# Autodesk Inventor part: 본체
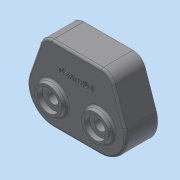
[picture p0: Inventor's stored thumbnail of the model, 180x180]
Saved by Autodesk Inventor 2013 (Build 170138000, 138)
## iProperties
Created: 2014-12
Part Number: 본체
Material: 일반
Document SubType Name: Modeling
Designer: dgall
Density: 1 g/cm^3
Author: dgall
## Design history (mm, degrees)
sketch "스케치1"
  geometry: L1 (0, 0)-(0, 36.035); L2 (0, 0)-(0, -46); L3 (0, 0)-(-32.527, -32.527); L4 (0, 0)-(32.527, -32.527); L5 (47, 36)-(-47, 36); L6 (-47, 36)-(-66.565, -20.803); L7 (47, 36)-(67.678, -24.037); L8 (-32.527, -68.527)-(32.527, -68.527); A1 r 46 centre (0, 0) between (-28.636, 36) and (28.636, 36); A2 r 36 centre (-32.527, -32.527) between (-66.565, -20.803) and (-32.527, -68.527); A3 r 36 centre (32.527, -32.527) between (32.527, -68.527) and (66.565, -20.803); 2 further points
  constraints: 16 end point, 9 point on circle, 3 centre point, 3 coincident, 3 point on line, 3 tangent, 1 collinear, 1 midpoint, 1 parallel, 1 perpendicular, 1 vertical, 1 vertical alignment
  dimensions: "d0" = 46 radius of A1; "d4" = 45 deg angle of L2 L3; "d6" = 45 deg angle of L4 L2; "d8" = 36 radius of A2; "d9" = 94 distance of L5.start L5.end; "d10" = 36 distance from line of L5 point (0, 0); "d11" = 36 radius of A3
extrude "돌출1" new body sketch "스케치1" distance "d12" = 44; taper "d13" = 0 deg
sketch "스케치2"
  geometry: L1 (-47, 36)-(47, 36) reference; L2 (-66.565, -20.803)-(-47, 36) reference; L3 (32.527, -68.527)-(-32.527, -68.527) reference; L4 (47, 36)-(66.565, -20.803) reference; L5 (43.434, 31)-(-43.434, 31); L6 (-43.434, 31)-(-61.837, -22.432); L7 (-32.527, -63.527)-(32.527, -63.527); L8 (61.837, -22.432)-(43.434, 31); A1 r 36 centre (-32.527, -32.527) between (-66.565, -20.803) and (-32.527, -68.527) reference; A2 r 36 centre (32.527, -32.527) between (32.527, -68.527) and (66.565, -20.803) reference; A3 r 31 centre (-32.527, -32.527) between (-61.837, -22.432) and (-32.527, -63.527); A4 r 31 centre (32.527, -32.527) between (32.527, -63.527) and (61.837, -22.432); 1 further point
  constraints: 8 end point, 4 point on circle, 2 centre point, 5 other
  dimensions: "d14" = 5 distance between parallel lines of L1 L5
extrude "돌출2" cut sketch "스케치2" distance "d15" = 34; taper "d16" = 0 deg
sketch "스케치3"
  geometry: A1 r 31 centre (-32.527, -32.527) between (-61.837, -22.432) and (-32.527, -63.527) reference; A2 r 31 centre (32.527, -32.527) between (32.527, -63.527) and (61.837, -22.432) reference; A3 r 24 centre (-32.527, -32.527) between (-26.959, -9.182) and (-9.182, -26.959); A4 r 24 centre (32.527, -32.527) between (9.182, -26.959) and (26.959, -9.182); A5 r 3 centre (-26.263, -6.263) between (-26.959, -9.182) and (-23.345, -5.568); A6 r 3 centre (26.263, -6.263) between (23.345, -5.568) and (26.959, -9.182); A7 r 3 centre (-6.263, -26.263) between (-5.568, -23.345) and (-9.182, -26.959); A8 r 3 centre (6.263, -26.263) between (9.182, -26.959) and (5.568, -23.345); A9 r 24 centre (0, 0) between (-5.568, -23.345) and (5.568, -23.345); A10 r 24 centre (0, 0) between (23.345, -5.568) and (-23.345, -5.568); 1 further point
  constraints: 16 point on circle, 8 centre point, 8 tangent, 3 coincident
  dimensions: "d19" = 48 diameter of A4; "d20" = 48 diameter of A3; "d21" = 3 radius of A5; "d22" = 3 radius of A8; "d23" = 3 radius of A7; "d24" = 3 radius of A6; "d25" = 24 radius of A10; "d26" = 24 radius of A9
extrude "돌출3" join sketch "스케치3" distance "d27" = 11; taper "d28" = 0 deg
hole "구멍1" diameter "d31" = 40; stored, may be unused: countersink angle "d35" = 90 deg, drill point angle "d37" = 0 deg; dims "d29" = 10, "d30" = 10, "d32" = 6, "d33" = 4, "d34" = 2, "d36" = 12
hole "구멍2" diameter "d40" = 20; stored, may be unused: countersink angle "d44" = 90 deg, drill point angle "d46" = 0 deg; dims "d38" = 10, "d39" = 10, "d41" = 6, "d42" = 4, "d43" = 2, "d45" = 3
hole "구멍3" diameter "d49" = 15.5; stored, may be unused: countersink angle "d53" = 90 deg, drill point angle "d55" = 0 deg; dims "d47" = 10, "d48" = 10, "d50" = 6, "d51" = 35, "d52" = 11, "d54" = 21
hole "구멍4" diameter "d58" = 15.5; stored, may be unused: countersink angle "d62" = 90 deg, drill point angle "d64" = 0 deg; dims "d56" = 10, "d57" = 10, "d59" = 6, "d60" = 35, "d61" = 11, "d63" = 21
sketch "스케치4"
  geometry: C1 r 7.75 at (-32.527, 32.527) reference; C2 r 7.75 at (32.527, 32.527) reference; C3 r 20 at (-32.527, 32.527); C4 r 20 at (32.527, 32.527); A1 r 36 centre (32.527, 32.527) between (66.565, 20.803) and (32.527, 68.527) reference; A2 r 36 centre (-32.527, 32.527) between (-32.527, 68.527) and (-66.565, 20.803) reference; 1 further point
  constraints: 2 centre point, 2 coincident, 1 equal radius
  dimensions: "d65" = 40 diameter of C4
extrude "돌출4" join sketch "스케치4" distance "d67" = 7; taper "d68" = 0 deg
hole "구멍5" diameter "d71" = 30; stored, may be unused: countersink angle "d75" = 90 deg, drill point angle "d77" = 0 deg; dims "d69" = 10, "d70" = 10, "d72" = 6, "d73" = 10, "d74" = 11, "d76" = 7
hole "구멍6" diameter "d80" = 30; stored, may be unused: countersink angle "d84" = 90 deg, drill point angle "d86" = 0 deg; dims "d78" = 10, "d79" = 10, "d81" = 6, "d82" = 10, "d83" = 11, "d85" = 7
sketch "스케치5"
  geometry: L1 (-47, -36)-(47, -36) reference; 2 further points
  constraints: 1 vertical alignment, 1 other
  dimensions: "d87" = 30 distance from line of point (0, -6) L1
extrude "돌출5" join sketch "스케치5" distance "d88" = 1; taper "d89" = 0 deg
node "작업 평면1"
  node "작업축1"
sketch "스케치6"
  geometry: L1 (3.5, 15)-(3.5, -15) reference; L2 (-3.5, -7.75)-(-3.5, 7.75) reference; L3 (-3.5, 0)-(3.5, 0); L4 (-3.5, -15)-(-3.5, 15) reference; L5 (-3.5, -68.527)-(-3.5, -11.723) reference; L6 (-3.5, -20)-(3.718, -20); L7 (3.718, -20)-(3.718, -18.727); L8 (3.718, -18.727)-(-3.5, -20); 1 further point
  constraints: 8 end point, 2 midpoint, 2 perpendicular, 1 point on line
  dimensions: "d91" = 40 diameter of L6 L3; "d93" = 100 deg angle of L8 L5; "d95" = 1.27278 distance of L6.end L7.end
revolve "회전1" sketch "스케치6" stored, may be unused: angle "d96" = 90 deg
node "작업 평면2"
  node "작업축2"
sketch "스케치7"
  geometry: 1 further point
node "작업 평면3"
sketch "스케치8"
  geometry: L1 (-61.837, -22.432)-(-43.434, 31) reference; L2 (43.434, 31)-(61.837, -22.432) reference; L3 (32.527, -63.527)-(-32.527, -63.527) reference; L4 (-47, 36)-(47, 36) reference; L5 (32.527, -68.527)-(-32.527, -68.527) reference; L6 (0, 36)-(0, 7); L7 (0, 7)-(51.7, 7); L8 (0, 7)-(-51.7, 7); A1 r 8 centre (51.7, 7) between (49.095, 14.564) and (54.305, -0.564); A2 r 8 centre (0, -63.527) between (8, -63.527) and (-8, -63.527); A3 r 8 centre (-51.7, 7) between (-54.305, -0.564) and (-49.095, 14.564); 1 further point
  constraints: 8 point on line, 6 end point, 6 point on circle, 3 centre point, 2 coincident, 2 equal radius, 2 midpoint, 2 perpendicular, 1 collinear
  dimensions: "d105" = 8 radius of A1; "d106" = 29 distance of L6.start L6.end
extrude "돌출6" join sketch "스케치8" distance "d107" = 34; taper "d108" = 0 deg
fillet "모깎기1" dims "d109" = 3
fillet "모깎기2" dims "d110" = 18
hole "구멍7" diameter "d113" = 4.134; stored, may be unused: countersink angle "d117" = 90 deg, drill point angle "d119" = 118 deg; dims "d111" = 10, "d112" = 10, "d114" = 20, "d115" = 10, "d116" = 11, "d118" = 23
hole "구멍8" diameter "d122" = 4.134; stored, may be unused: countersink angle "d126" = 90 deg, drill point angle "d128" = 118 deg; dims "d120" = 10, "d121" = 10, "d123" = 20, "d124" = 10, "d125" = 11, "d127" = 23
hole "구멍9" diameter "d131" = 4.134; stored, may be unused: countersink angle "d135" = 90 deg, drill point angle "d137" = 118 deg; dims "d129" = 10, "d130" = 10, "d132" = 20, "d133" = 10, "d134" = 11, "d136" = 23
fillet "모깎기3" dims "d138" = 0.3
fillet "모깎기4" dims "d139" = 0.1
fillet "모깎기5" dims "d140" = 0.3
node "솔리드1"
mirror "대칭1"
other parameters: "d17" = 48, "d90" = 90 deg, "d97" = 90 deg, "d98" = 0
